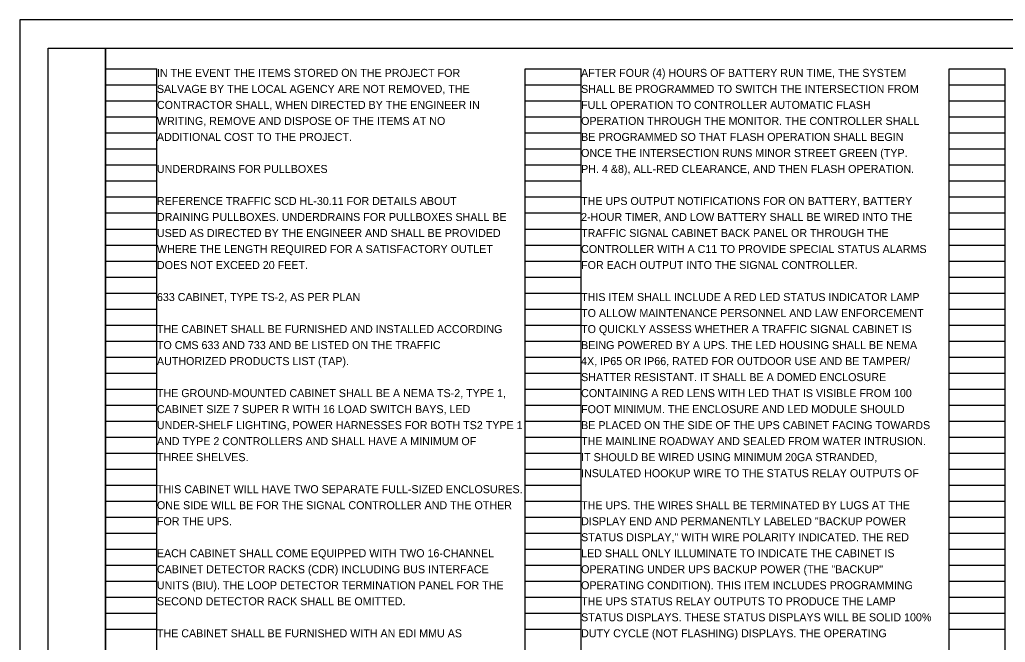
# Model space of a CAD drawing. Extents: x 0 to 34, y 0 to 22.
# Drawn here: x 0 to 17.24, y 11.11 to 22 of the extents above; entities that cross this region are included whole.
import ezdxf

# ---------------------------------------------------------------- set-up
doc = ezdxf.new("R2010")
doc.units = 0
for name, color, linetype in [('SH_Border', 7, 'Continuous'), ('SH_Cut_Line', 7, 'Continuous'), ('SH_Data', 7, 'Continuous'), ('SH_Text', 7, 'Continuous')]:
    doc.layers.add(name, color=color, linetype=linetype)

msp = doc.modelspace()

# ---------------------------------------------------------------- linework, layer by layer
at = {"layer": 'SH_Border'}
for points in [[(0.5, 21.5), (1.5, 21.5), (1.5, 0.5), (0.5, 0.5)], [(1.5, 21.5), (33.5, 21.5), (33.5, 0.5), (1.5, 0.5)]]:
    msp.add_lwpolyline(points, close=True, dxfattribs=at)
at = {"layer": 'SH_Cut_Line'}
msp.add_lwpolyline([(0, 0), (34, 0), (34, 22), (0, 22)], close=True, dxfattribs=at)
at = {"layer": 'SH_Data'}
for p, q in [((1.5, 0.98), (1.5, 21.14)), ((1.5, 21.14), (2.4, 21.14)), ((2.4, 0.98), (2.4, 21.14)), ((8.84, 0.98), (8.84, 21.14)), ((8.84, 21.14), (9.82, 21.14)), ((9.82, 0.98), (9.82, 21.14)), ((16.26, 0.98), (16.26, 21.14)), ((16.26, 21.14), (17.24, 21.14)), ((17.24, 0.98), (17.24, 21.14)), ((1.5, 20.86), (2.4, 20.86)), ((8.84, 20.86), (9.82, 20.86)), ((16.26, 20.86), (17.24, 20.86)), ((1.5, 20.58), (2.4, 20.58)), ((8.84, 20.58), (9.82, 20.58)), ((16.26, 20.58), (17.24, 20.58)), ((1.5, 20.3), (2.4, 20.3)), ((8.84, 20.3), (9.82, 20.3)), ((16.26, 20.3), (17.24, 20.3)), ((1.5, 20.02), (2.4, 20.02)), ((8.84, 20.02), (9.82, 20.02)), ((16.26, 20.02), (17.24, 20.02)), ((1.5, 19.74), (2.4, 19.74)), ((8.84, 19.74), (9.82, 19.74)), ((16.26, 19.74), (17.24, 19.74)), ((1.5, 19.46), (2.4, 19.46)), ((8.84, 19.46), (9.82, 19.46)), ((16.26, 19.46), (17.24, 19.46)), ((1.5, 19.18), (2.4, 19.18)), ((8.84, 19.18), (9.82, 19.18)), ((16.26, 19.18), (17.24, 19.18)), ((1.5, 18.9), (2.4, 18.9)), ((8.84, 18.9), (9.82, 18.9)), ((16.26, 18.9), (17.24, 18.9)), ((1.5, 18.62), (2.4, 18.62)), ((8.84, 18.62), (9.82, 18.62)), ((16.26, 18.62), (17.24, 18.62)), ((1.5, 18.34), (2.4, 18.34)), ((8.84, 18.34), (9.82, 18.34)), ((16.26, 18.34), (17.24, 18.34)), ((1.5, 18.06), (2.4, 18.06)), ((8.84, 18.06), (9.82, 18.06)), ((16.26, 18.06), (17.24, 18.06)), ((1.5, 17.78), (2.4, 17.78)), ((8.84, 17.78), (9.82, 17.78)), ((16.26, 17.78), (17.24, 17.78)), ((1.5, 17.5), (2.4, 17.5)), ((8.84, 17.5), (9.82, 17.5)), ((16.26, 17.5), (17.24, 17.5)), ((1.5, 17.22), (2.4, 17.22)), ((8.84, 17.22), (9.82, 17.22)), ((16.26, 17.22), (17.24, 17.22)), ((1.5, 16.94), (2.4, 16.94)), ((8.84, 16.94), (9.82, 16.94)), ((16.26, 16.94), (17.24, 16.94)), ((1.5, 16.66), (2.4, 16.66)), ((8.84, 16.66), (9.82, 16.66)), ((16.26, 16.66), (17.24, 16.66)), ((1.5, 16.38), (2.4, 16.38)), ((8.84, 16.38), (9.82, 16.38)), ((16.26, 16.38), (17.24, 16.38)), ((1.5, 16.1), (2.4, 16.1)), ((8.84, 16.1), (9.82, 16.1)), ((16.26, 16.1), (17.24, 16.1)), ((1.5, 15.82), (2.4, 15.82)), ((8.84, 15.82), (9.82, 15.82)), ((16.26, 15.82), (17.24, 15.82)), ((1.5, 15.54), (2.4, 15.54)), ((8.84, 15.54), (9.82, 15.54)), ((16.26, 15.54), (17.24, 15.54)), ((1.5, 15.26), (2.4, 15.26)), ((8.84, 15.26), (9.82, 15.26)), ((16.26, 15.26), (17.24, 15.26)), ((1.5, 14.98), (2.4, 14.98)), ((8.84, 14.98), (9.82, 14.98)), ((16.26, 14.98), (17.24, 14.98)), ((1.5, 14.7), (2.4, 14.7)), ((8.84, 14.7), (9.82, 14.7)), ((16.26, 14.7), (17.24, 14.7)), ((1.5, 14.42), (2.4, 14.42)), ((8.84, 14.42), (9.82, 14.42)), ((16.26, 14.42), (17.24, 14.42)), ((1.5, 14.14), (2.4, 14.14)), ((8.84, 14.14), (9.82, 14.14)), ((16.26, 14.14), (17.24, 14.14)), ((1.5, 13.86), (2.4, 13.86)), ((8.84, 13.86), (9.82, 13.86)), ((16.26, 13.86), (17.24, 13.86)), ((1.5, 13.58), (2.4, 13.58)), ((8.84, 13.58), (9.82, 13.58)), ((16.26, 13.58), (17.24, 13.58)), ((1.5, 13.3), (2.4, 13.3)), ((8.84, 13.3), (9.82, 13.3)), ((16.26, 13.3), (17.24, 13.3)), ((1.5, 13.02), (2.4, 13.02)), ((8.84, 13.02), (9.82, 13.02)), ((16.26, 13.02), (17.24, 13.02)), ((1.5, 12.74), (2.4, 12.74)), ((8.84, 12.74), (9.82, 12.74)), ((16.26, 12.74), (17.24, 12.74)), ((1.5, 12.46), (2.4, 12.46)), ((8.84, 12.46), (9.82, 12.46)), ((16.26, 12.46), (17.24, 12.46)), ((1.5, 12.18), (2.4, 12.18)), ((8.84, 12.18), (9.82, 12.18)), ((16.26, 12.18), (17.24, 12.18)), ((1.5, 11.9), (2.4, 11.9)), ((8.84, 11.9), (9.82, 11.9)), ((16.26, 11.9), (17.24, 11.9)), ((1.5, 11.62), (2.4, 11.62)), ((8.84, 11.62), (9.82, 11.62)), ((16.26, 11.62), (17.24, 11.62)), ((1.5, 11.34), (2.4, 11.34)), ((8.84, 11.34), (9.82, 11.34)), ((16.26, 11.34), (17.24, 11.34))]:
    msp.add_line(p, q, dxfattribs=at)

# ---------------------------------------------------------------- texts
at = {"layer": 'SH_Text'}
for s, p in [('IN THE EVENT THE ITEMS STORED ON THE PROJECT FOR', (2.4, 21)), ('AFTER FOUR (4) HOURS OF BATTERY RUN TIME, THE SYSTEM', (9.82, 21)), ('SALVAGE BY THE LOCAL AGENCY ARE NOT REMOVED, THE', (2.4, 20.72)), ('SHALL BE PROGRAMMED TO SWITCH THE INTERSECTION FROM', (9.82, 20.72)), ('CONTRACTOR SHALL, WHEN DIRECTED BY THE ENGINEER IN', (2.4, 20.44)), ('FULL OPERATION TO CONTROLLER AUTOMATIC FLASH', (9.82, 20.44)), ('WRITING, REMOVE AND DISPOSE OF THE ITEMS AT NO', (2.4, 20.16)), ('OPERATION THROUGH THE MONITOR. THE CONTROLLER SHALL', (9.82, 20.16)), ('ADDITIONAL COST TO THE PROJECT.', (2.4, 19.88)), ('BE PROGRAMMED SO THAT FLASH OPERATION SHALL BEGIN', (9.82, 19.88)), ('ONCE THE INTERSECTION RUNS MINOR STREET GREEN (TYP.', (9.82, 19.6)), ('UNDERDRAINS FOR PULLBOXES', (2.4, 19.32)), ('PH. 4 &8), ALL-RED CLEARANCE, AND THEN FLASH OPERATION.', (9.82, 19.32)), ('REFERENCE TRAFFIC SCD HL-30.11 FOR DETAILS ABOUT', (2.4, 18.76)), ('THE UPS OUTPUT NOTIFICATIONS FOR ON BATTERY, BATTERY', (9.82, 18.76)), ('DRAINING PULLBOXES. UNDERDRAINS FOR PULLBOXES SHALL BE', (2.4, 18.48)), ('2-HOUR TIMER, AND LOW BATTERY SHALL BE WIRED INTO THE', (9.82, 18.48)), ('USED AS DIRECTED BY THE ENGINEER AND SHALL BE PROVIDED', (2.4, 18.2)), ('TRAFFIC SIGNAL CABINET BACK PANEL OR THROUGH THE', (9.82, 18.2)), ('WHERE THE LENGTH REQUIRED FOR A SATISFACTORY OUTLET', (2.4, 17.92)), ('CONTROLLER WITH A C11 TO PROVIDE SPECIAL STATUS ALARMS', (9.82, 17.92)), ('DOES NOT EXCEED 20 FEET.', (2.4, 17.64)), ('FOR EACH OUTPUT INTO THE SIGNAL CONTROLLER.', (9.82, 17.64)), ('633 CABINET, TYPE TS-2, AS PER PLAN', (2.4, 17.08)), ('THIS ITEM SHALL INCLUDE A RED LED STATUS INDICATOR LAMP', (9.82, 17.08)), ('TO ALLOW MAINTENANCE PERSONNEL AND LAW ENFORCEMENT', (9.82, 16.8)), ('THE CABINET SHALL BE FURNISHED AND INSTALLED ACCORDING', (2.4, 16.52)), ('TO QUICKLY ASSESS WHETHER A TRAFFIC SIGNAL CABINET IS', (9.82, 16.52)), ('TO CMS 633 AND 733 AND BE LISTED ON THE TRAFFIC', (2.4, 16.24)), ('BEING POWERED BY A UPS. THE LED HOUSING SHALL BE NEMA', (9.82, 16.24)), ('AUTHORIZED PRODUCTS LIST (TAP).', (2.4, 15.96)), ('4X, IP65 OR IP66, RATED FOR OUTDOOR USE AND BE TAMPER/', (9.82, 15.96)), ('SHATTER RESISTANT. IT SHALL BE A DOMED ENCLOSURE', (9.82, 15.68)), ('THE GROUND-MOUNTED CABINET SHALL BE A NEMA TS-2, TYPE 1,', (2.4, 15.4)), ('CONTAINING A RED LENS WITH LED THAT IS VISIBLE FROM 100', (9.82, 15.4)), ('CABINET SIZE 7 SUPER R WITH 16 LOAD SWITCH BAYS, LED ', (2.4, 15.12)), ('FOOT MINIMUM. THE ENCLOSURE AND LED MODULE SHOULD', (9.82, 15.12)), ('UNDER-SHELF LIGHTING, POWER HARNESSES FOR BOTH TS2 TYPE 1', (2.4, 14.84)), ('BE PLACED ON THE SIDE OF THE UPS CABINET FACING TOWARDS', (9.82, 14.84)), ('AND TYPE 2 CONTROLLERS AND SHALL HAVE A MINIMUM OF ', (2.4, 14.56)), ('THE MAINLINE ROADWAY AND SEALED FROM WATER INTRUSION.', (9.82, 14.56)), ('THREE SHELVES.', (2.4, 14.28)), ('IT SHOULD BE WIRED USING MINIMUM 20GA STRANDED,', (9.82, 14.28)), ('INSULATED HOOKUP WIRE TO THE STATUS RELAY OUTPUTS OF', (9.82, 14)), ('THIS CABINET WILL HAVE TWO SEPARATE FULL-SIZED ENCLOSURES.', (2.4, 13.72)), ('ONE SIDE WILL BE FOR THE SIGNAL CONTROLLER AND THE OTHER', (2.4, 13.44)), ('THE UPS. THE WIRES SHALL BE TERMINATED BY LUGS AT THE', (9.82, 13.44)), ('FOR THE UPS.', (2.4, 13.16)), ('DISPLAY END AND PERMANENTLY LABELED "BACKUP POWER', (9.82, 13.16)), ('STATUS DISPLAY," WITH WIRE POLARITY INDICATED. THE RED', (9.82, 12.88)), ('EACH CABINET SHALL COME EQUIPPED WITH TWO 16-CHANNEL', (2.4, 12.6)), ('LED SHALL ONLY ILLUMINATE TO INDICATE THE CABINET IS', (9.82, 12.6)), ('CABINET DETECTOR RACKS (CDR) INCLUDING BUS INTERFACE', (2.4, 12.32)), ('OPERATING UNDER UPS BACKUP POWER (THE "BACKUP"', (9.82, 12.32)), ('UNITS (BIU). THE LOOP DETECTOR TERMINATION PANEL FOR THE', (2.4, 12.04)), ('OPERATING CONDITION). THIS ITEM INCLUDES PROGRAMMING', (9.82, 12.04)), ('SECOND DETECTOR RACK SHALL BE OMITTED.', (2.4, 11.76)), ('THE UPS STATUS RELAY OUTPUTS TO PRODUCE THE LAMP', (9.82, 11.76)), ('STATUS DISPLAYS. THESE STATUS DISPLAYS WILL BE SOLID 100%', (9.82, 11.48)), ('THE CABINET SHALL BE FURNISHED WITH AN EDI MMU AS', (2.4, 11.2)), ('DUTY CYCLE (NOT FLASHING) DISPLAYS. THE OPERATING', (9.82, 11.2))]:
    msp.add_text(s, height=0.14, dxfattribs=at).set_placement(p)

doc.saveas('drawing.dxf')
